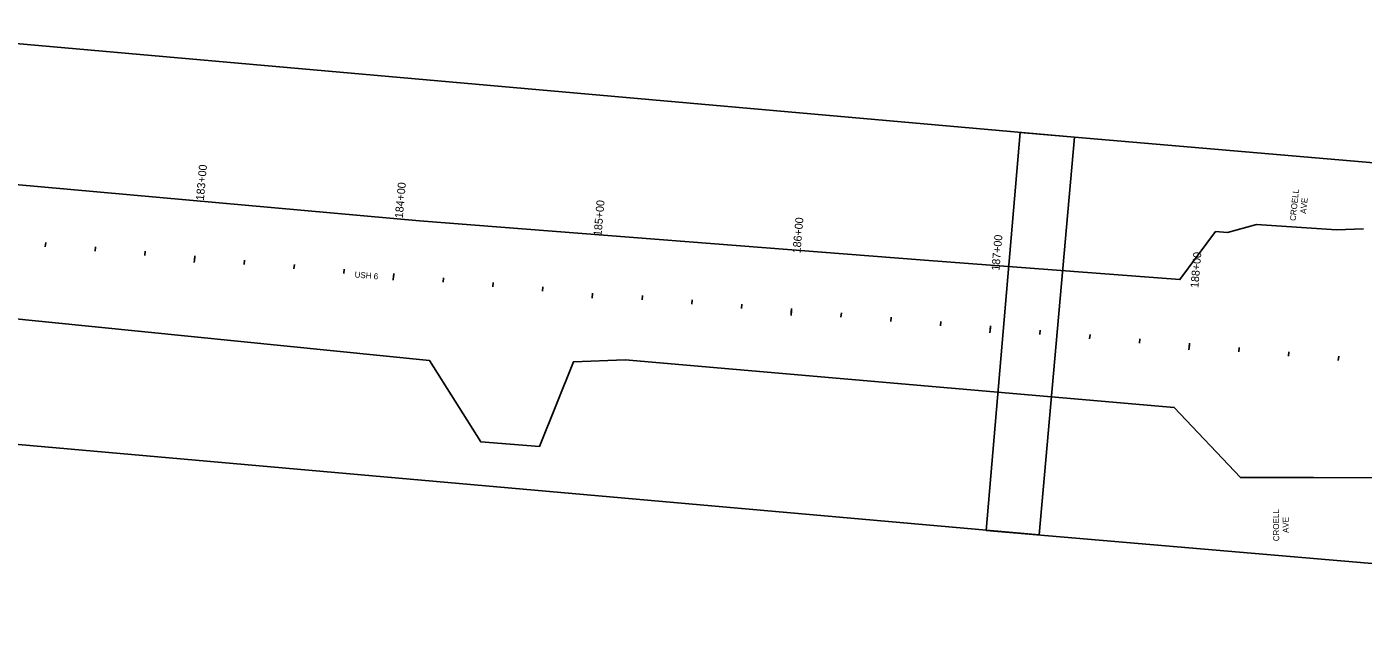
# Model space of a CAD drawing. Extents: x 20499876 to 20505320, y 7953544 to 7954108.
# Drawn here: x 20501924 to 20502593, y 7953684 to 7953990 of the extents above; entities that cross this region are included whole.
import ezdxf

# ---------------------------------------------------------------- set-up
doc = ezdxf.new("R2010")
doc.units = 0
for name, color, linetype in [('Draft_0', 7, 'Continuous'), ('Draft_7', 7, 'Continuous'), ('Drainage- Pipe', 7, 'Continuous'), ('PS_CONST', 7, 'Continuous'), ('Wall', 7, 'Continuous')]:
    doc.layers.add(name, color=color, linetype=linetype)

msp = doc.modelspace()

# ---------------------------------------------------------------- linework, layer by layer
at = {"layer": 'Draft_7'}
for p, q in [((20501932.88, 7953879.57), (20501933.08, 7953881.75)), ((20501957.79, 7953877.34), (20501957.98, 7953879.52)), ((20501982.69, 7953875.11), (20501982.88, 7953877.29)), ((20502007.7, 7953874.1), (20502007.48, 7953871.66)), ((20502032.49, 7953870.65), (20502032.68, 7953872.83)), ((20502057.39, 7953868.42), (20502057.58, 7953870.6)), ((20502082.29, 7953866.19), (20502082.48, 7953868.37)), ((20502107.3, 7953865.18), (20502107.08, 7953862.74)), ((20502132.09, 7953861.73), (20502132.28, 7953863.91)), ((20502156.99, 7953859.5), (20502157.18, 7953861.68)), ((20502181.89, 7953857.27), (20502182.08, 7953859.45)), ((20502206.9, 7953856.27), (20502206.68, 7953853.84)), ((20502231.7, 7953852.89), (20502231.89, 7953855.06)), ((20502256.6, 7953850.72), (20502256.79, 7953852.9)), ((20502281.51, 7953848.55), (20502281.7, 7953850.73)), ((20502306.52, 7953847.6), (20502306.31, 7953845.17)), ((20502331.32, 7953844.22), (20502331.51, 7953846.39)), ((20502356.23, 7953842.05), (20502356.41, 7953844.23)), ((20502381.13, 7953839.88), (20502381.32, 7953842.06)), ((20502406.14, 7953838.94), (20502405.93, 7953836.5)), ((20502430.94, 7953835.55), (20502431.13, 7953837.72)), ((20502455.85, 7953833.38), (20502456.04, 7953835.56)), ((20502480.75, 7953831.21), (20502480.94, 7953833.39)), ((20502505.77, 7953830.27), (20502505.55, 7953827.83)), ((20502530.57, 7953826.88), (20502530.76, 7953829.05)), ((20502555.47, 7953824.71), (20502555.66, 7953826.89)), ((20502580.38, 7953822.54), (20502580.57, 7953824.72))]:
    msp.add_line(p, q, dxfattribs=at)
at = {"layer": 'Drainage- Pipe'}
for points in [[(20501823.68, 7953989.74), (20501806.03, 7953790.52), (20502430.58, 7953735.18), (20502448.23, 7953934.4)], [(20502421.05, 7953936.77), (20502403.97, 7953737.5), (20503028.68, 7953683.95), (20503045.76, 7953883.22)]]:
    msp.add_lwpolyline(points, close=True, dxfattribs=at)
at = {"layer": 'PS_CONST'}
for p, q in [((20502007.59, 7953872.88), (20502007.78, 7953875.06)), ((20502107.19, 7953863.96), (20502107.38, 7953866.14)), ((20502206.9, 7953856.27), (20502206.68, 7953853.84)), ((20502306.41, 7953846.39), (20502306.6, 7953848.56)), ((20502406.04, 7953837.72), (20502406.23, 7953839.89)), ((20502505.66, 7953829.05), (20502505.85, 7953831.22))]:
    msp.add_line(p, q, dxfattribs=at)
at = {"layer": 'Wall'}
for points in [[(20500961.05, 7953985.49), (20501585.27, 7953936.81), (20501724.91, 7953925.27), (20501728.32, 7953926.51), (20501728.73, 7953931.44), (20501735.34, 7953931.05), (20501745.91, 7953953.5), (20501775.93, 7953950.79), (20501843.37, 7953917.33), (20502120.24, 7953892.49), (20502373.22, 7953872.83), (20502501.07, 7953863.11), (20502518.94, 7953887.24), (20502524.88, 7953886.71), (20502539.39, 7953890.66), (20502579.49, 7953887.98), (20502593.01, 7953888.5)], [(20502805.68, 7953763.59), (20502567.99, 7953764), (20502531.37, 7953763.95), (20502498.2, 7953799.08), (20502223.25, 7953822.85), (20502197.43, 7953821.94), (20502180.3, 7953779.46), (20502150.9, 7953781.82), (20502125.33, 7953822.5), (20501909.53, 7953844.31)]]:
    msp.add_lwpolyline(points, dxfattribs=at)

# ---------------------------------------------------------------- texts
at = {"layer": 'Draft_0'}
for s, rotation, p in [('CROELL', 84.04085, (20502559.02, 7953892.37)), ('AVE', 84.04085, (20502564.22, 7953895.93)), ('USH 6', 355, (20502087.67, 7953864.2)), ('CROELL', 90.58727, (20502550.78, 7953732.06)), ('AVE', 90.58727, (20502555.54, 7953736.2))]:
    msp.add_text(s, height=3, rotation=rotation, dxfattribs=at).set_placement(p)
at = {"layer": 'Draft_7'}
for s, rotation, p in [('183+00', 84.88337, (20502012.26, 7953902.58)), ('184+00', 84.88337, (20502111.86, 7953893.66)), ('185+00', 85.02642, (20502211.39, 7953884.77)), ('186+00', 85.02642, (20502311.01, 7953876.1)), ('187+00', 85.02642, (20502410.63, 7953867.43)), ('188+00', 85.02642, (20502510.26, 7953858.76))]:
    msp.add_text(s, height=4.008, rotation=rotation, dxfattribs=at).set_placement(p)
at = {"layer": 'PS_CONST'}
msp.add_text('185+00', height=4.008, rotation=85.02642, dxfattribs=at).set_placement((20502211.39, 7953884.77))

doc.saveas('drawing.dxf')
